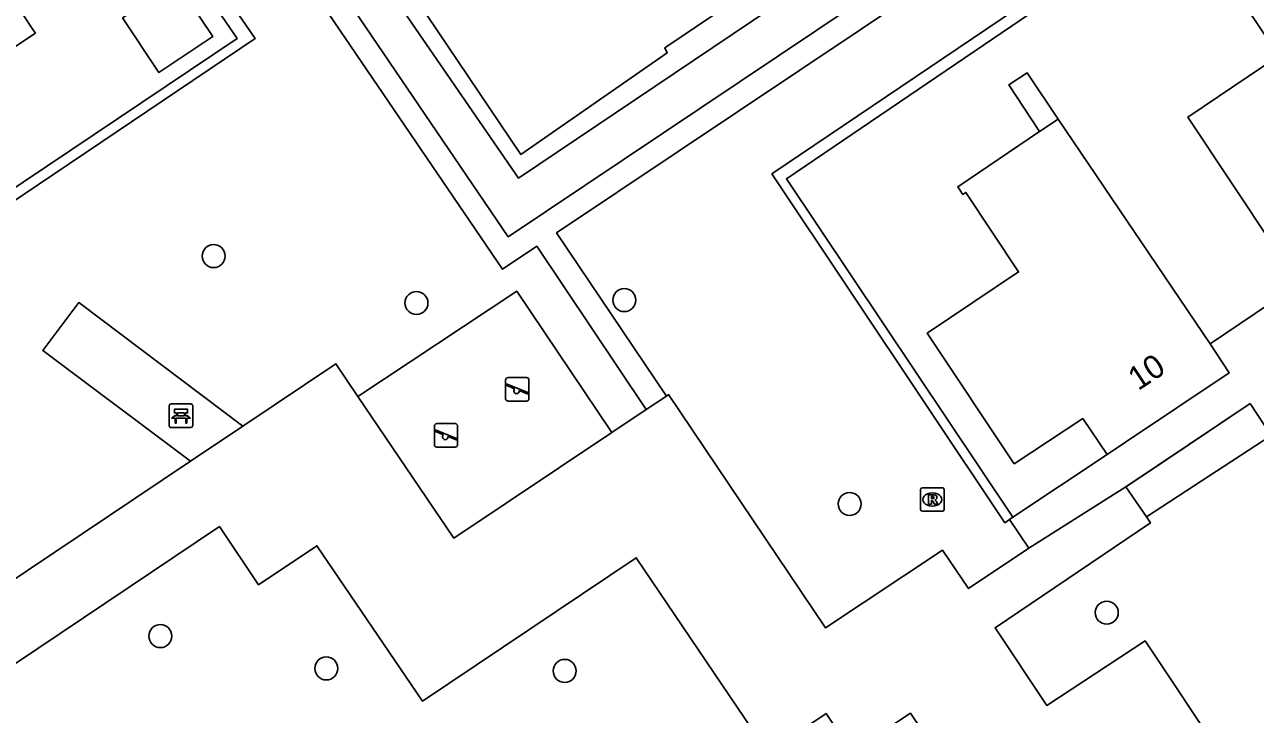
# Model space of a CAD drawing. Extents: x 158797 to 159887, y 384318 to 385255.
# Drawn here: x 158996.3 to 159048.7, y 384605 to 384634.4 of the extents above; entities that cross this region are included whole.
import ezdxf

# ---------------------------------------------------------------- set-up
doc = ezdxf.new("R2010")
doc.units = 0
for name, color, linetype in [('IMGEO_Bank', 7, 'Continuous'), ('IMGEO_Boom', 7, 'Continuous'), ('IMGEO_Groenvoorziening', 7, 'Continuous'), ('IMGEO_Haag', 7, 'Continuous'), ('IMGEO_Pand', 7, 'Continuous'), ('IMGEO_Pand_nummerreeks', 7, 'Continuous'), ('IMGEO_Rijbaan_lokaal_open', 7, 'Continuous'), ('IMGEO_Rioolput', 7, 'Continuous'), ('IMGEO_Speelvoorziening', 7, 'Continuous'), ('IMGEO_Voetpad_gesloten', 7, 'Continuous'), ('IMGEO_Voetpad_halfverhard', 7, 'Continuous'), ('IMGEO_Voetpad_open', 7, 'Continuous')]:
    doc.layers.add(name, color=color, linetype=linetype)

msp = doc.modelspace()

# ---------------------------------------------------------------- linework, layer by layer
at = {"layer": 'IMGEO_Bank'}
for p, q in [((159002.463, 384617.317), (159002.463, 384618.158)), ((159002.463, 384618.158), (159002.463, 384617.317)), ((159002.538, 384618.242), (159003.379, 384618.242)), ((159003.379, 384618.242), (159002.538, 384618.242)), ((159003.463, 384618.167), (159003.463, 384617.326)), ((159003.463, 384617.326), (159003.463, 384618.167)), ((159003.16, 384617.64), (159002.767, 384617.64)), ((159002.772, 384617.748), (159002.772, 384617.854)), ((159002.816, 384617.854), (159002.816, 384617.748)), ((159003.104, 384617.86), (159002.822, 384617.86)), ((159002.822, 384617.742), (159003.104, 384617.742)), ((159003.11, 384617.748), (159003.11, 384617.854)), ((159003.154, 384617.854), (159003.154, 384617.748)), ((159003.388, 384617.242), (159002.547, 384617.242)), ((159002.547, 384617.242), (159003.388, 384617.242))]:
    msp.add_line(p, q, dxfattribs=at)
for points in [[(159002.766, 384617.86), (159002.68, 384617.86), (159002.68, 384618.021), (159003.243, 384618.021), (159003.243, 384617.86), (159003.16, 384617.86)], [(159002.71, 384617.64), (159002.568, 384617.64), (159002.68, 384617.742), (159002.766, 384617.742)], [(159002.76, 384617.633), (159002.76, 384617.426), (159002.717, 384617.426), (159002.717, 384617.633)], [(159003.16, 384617.742), (159003.243, 384617.742), (159003.355, 384617.64), (159003.216, 384617.64)], [(159003.21, 384617.633), (159003.21, 384617.426), (159003.166, 384617.426), (159003.166, 384617.633)]]:
    msp.add_lwpolyline(points, dxfattribs=at)
for centre, radius, start, end in [((159002.541, 384618.164), 0.0779, 92.4484, 184.2845), ((159002.541, 384618.164), 0.0779, 92.4484, 184.2845), ((159003.385, 384618.164), 0.0779, 2.4484, 94.2845), ((159003.385, 384618.164), 0.0779, 2.4484, 94.2845), ((159002.71, 384617.633), 0.00671, 2.8957, 87.1043), ((159002.767, 384617.633), 0.00671, 92.8957, 177.1043), ((159002.765, 384617.853), 0.00671, 2.8957, 87.1043), ((159002.765, 384617.749), 0.00671, 272.8957, 357.1043), ((159002.822, 384617.853), 0.00671, 92.8957, 177.1043), ((159002.822, 384617.749), 0.00671, 182.8957, 267.1043), ((159003.104, 384617.853), 0.00671, 2.8957, 87.1043), ((159003.104, 384617.749), 0.00671, 272.8957, 357.1043), ((159003.161, 384617.853), 0.00671, 92.8957, 177.1043), ((159003.161, 384617.749), 0.00671, 182.8957, 267.1043), ((159003.159, 384617.633), 0.00671, 2.8957, 87.1043), ((159003.216, 384617.633), 0.00671, 92.8957, 177.1043), ((159002.541, 384617.32), 0.0779, 182.4484, 274.2845), ((159002.541, 384617.32), 0.0779, 182.4484, 274.2845), ((159003.385, 384617.32), 0.0779, 272.4484, 4.2845), ((159003.385, 384617.32), 0.0779, 272.4484, 4.2845)]:
    msp.add_arc(centre, radius, start, end, dxfattribs=at)
at = {"layer": 'IMGEO_Boom'}
for centre in [(159004.352, 384624.537), (159012.985, 384622.542), (159021.831, 384622.663), (159031.422, 384613.987), (159042.368, 384609.361), (159002.086, 384608.362), (159009.147, 384606.985), (159019.295, 384606.88)]:
    msp.add_circle(centre, 0.489, dxfattribs=at)
at = {"layer": 'IMGEO_Groenvoorziening'}
msp.add_lwpolyline([(159010.495, 384618.567), (159017.257, 384623.039), (159021.302, 384617.031)], dxfattribs=at)
at = {"layer": 'IMGEO_Haag'}
for points in [[(158982.198, 384627.503), (158986.877, 384630.783), (158991.18, 384624.297), (159005.347, 384633.805), (158997.226, 384645.658), (158986.56, 384661.35), (158977.807, 384655.577), (158970.042, 384650.292), (158941.462, 384692.581), (158927.478, 384683.208), (158931.293, 384677.308), (158928.892, 384675.59), (158929.234, 384675.051), (158928.67, 384674.688)], [(158982.566, 384626.956), (158986.69, 384629.795), (158990.973, 384623.592), (159006.114, 384633.802), (158986.551, 384662.087), (158978.394, 384656.739)], [(159074.64, 384658.987), (159074.434, 384659.327), (159072.046, 384657.677), (159028.116, 384628.032), (159038.03, 384613.181), (159038.222, 384613.33)], [(159038.372, 384613.43), (159028.729, 384627.821), (159074.64, 384658.987)], [(159000.221, 384652.861), (159003.802, 384647.511), (159004.201, 384646.941), (159017.33, 384627.856), (159035.525, 384640.095)], [(159031.062, 384645.764), (159034.39, 384640.711), (159023.558, 384633.403), (159023.653, 384633.188), (159017.434, 384628.858), (159004.937, 384647.41), (159004.913, 384647.446), (159005.369, 384647.758)], [(159048.477, 384618.263), (159044.057, 384615.293), (159043.177, 384614.715)], [(159049.365, 384616.904), (159044.054, 384613.436)]]:
    msp.add_lwpolyline(points, dxfattribs=at)
at = {"layer": 'IMGEO_Pand'}
for points in [[(158991.703, 384642.063), (158994.839, 384644.19), (158998.241, 384639.175), (158995.841, 384637.547), (158997.222, 384635.511), (158996.22, 384634.844), (158996.69, 384634.138), (158996.762, 384634.03), (158993.28, 384631.711), (158993.235, 384631.778), (158992.738, 384632.525), (158988.616, 384629.78), (158986.429, 384633.035), (158983.044, 384630.761), (158980.677, 384634.281)], [(159050.433, 384638.855), (159047.117, 384636.683), (159047.338, 384636.359), (159047.443, 384636.432), (159049.695, 384633.062), (159045.826, 384630.454), (159049.515, 384624.898), (159052.429, 384626.817), (159053.468, 384625.292)], [(159000.476, 384634.674), (159002.023, 384632.35), (159004.317, 384633.878), (159002.77, 384636.201), (159000.476, 384634.674)], [(159040.305, 384630.369), (159038.975, 384632.341), (159038.199, 384631.831), (159039.511, 384629.835)], [(159040.305, 384630.369), (159039.511, 384629.835)], [(159046.764, 384620.801), (159040.305, 384630.369)], [(159039.511, 384629.835), (159036.024, 384627.492), (159036.244, 384627.165), (159036.366, 384627.247), (159038.618, 384623.867), (159034.718, 384621.253), (159038.429, 384615.697), (159041.343, 384617.618), (159042.391, 384616.096)], [(159042.391, 384616.096), (159043.171, 384616.618), (159047.583, 384619.57), (159046.764, 384620.801)]]:
    msp.add_lwpolyline(points, dxfattribs=at)
at = {"layer": 'IMGEO_Rijbaan_lokaal_open'}
for points in [[(159046.764, 384620.801), (159050.601, 384623.386), (159053.468, 384625.292)], [(159048.477, 384618.263), (159043.177, 384614.715)], [(159049.365, 384616.904), (159048.477, 384618.263)], [(159038.372, 384613.43), (159042.391, 384616.096)], [(159043.177, 384614.715), (159039.049, 384612.101)], [(159038.222, 384613.33), (159038.372, 384613.43)], [(159039.049, 384612.101), (159038.222, 384613.33)]]:
    msp.add_lwpolyline(points, dxfattribs=at)
at = {"layer": 'IMGEO_Rioolput'}
for p, q in [((159034.443, 384613.753), (159034.443, 384614.605)), ((159034.518, 384614.679), (159035.37, 384614.679)), ((159034.931, 384614.459), (159034.956, 384614.459)), ((159035.444, 384614.605), (159035.444, 384613.753)), ((159034.954, 384613.899), (159034.929, 384613.899)), ((159035.37, 384613.679), (159034.518, 384613.679))]:
    msp.add_line(p, q, dxfattribs=at)
for points in [[(159034.443, 384613.753), (159034.443, 384614.605)], [(159034.518, 384614.679), (159035.37, 384614.679)], [(159035.032, 384614.377), (159034.78, 384614.379), (159034.78, 384613.979)], [(159034.958, 384614.298), (159034.904, 384614.298), (159034.904, 384614.217)], [(159035.444, 384614.605), (159035.444, 384613.753)], [(159034.78, 384613.979), (159034.904, 384613.979), (159034.904, 384614.141), (159034.915, 384614.141)], [(159034.904, 384614.217), (159034.956, 384614.217)], [(159034.962, 384614.112), (159035.033, 384613.979), (159035.173, 384613.979), (159035.108, 384614.105)], [(159035.37, 384613.679), (159034.518, 384613.679)]]:
    msp.add_lwpolyline(points, dxfattribs=at)
for centre, radius, start, end in [((159034.52, 384614.603), 0.0765, 91.552, 178.448), ((159034.52, 384614.603), 0.0765, 91.552, 178.448), ((159034.964, 384614.202), 0.0964, 77.0061, 93.1865), ((159034.978, 384614.259), 0.0378, 276.6634, 79.6772), ((159035.031, 384614.267), 0.109, 350.3612, 89.416), ((159035.368, 384614.603), 0.0765, 1.552, 88.448), ((159035.368, 384614.603), 0.0765, 1.552, 88.448), ((159034.52, 384613.755), 0.0765, 181.552, 268.448), ((159034.52, 384613.755), 0.0765, 181.552, 268.448), ((159034.914, 384614.088), 0.0533, 26.0293, 88.6989), ((159034.94, 384614.406), 0.19, 274.7715, 282.9687), ((159035.029, 384614.267), 0.112, 277.5842, 350.9817), ((159035.013, 384614.052), 0.108, 29.5134, 73.7905), ((159035.368, 384613.755), 0.0765, 271.552, 358.448), ((159035.368, 384613.755), 0.0765, 271.552, 358.448)]:
    msp.add_arc(centre, radius, start, end, dxfattribs=at)
for centre, major_axis, ratio, start_param, end_param in [((159034.93, 384614.179), (-0.387, 0.002), 0.722429, 4.712389, 7.853982), ((159034.955, 384614.179), (-0.39, 0.002), 0.717154, 1.570796, 4.712389)]:
    msp.add_ellipse(centre, major_axis=major_axis, ratio=ratio, start_param=start_param, end_param=end_param, dxfattribs=at)
at = {"layer": 'IMGEO_Speelvoorziening'}
for p, q in [((159016.782, 384618.464), (159016.782, 384619.264)), ((159016.782, 384619.264), (159016.782, 384618.464)), ((159017.165, 384618.892), (159016.826, 384619.029)), ((159016.851, 384619.089), (159017.727, 384618.736)), ((159016.882, 384619.364), (159017.672, 384619.364)), ((159017.672, 384619.364), (159016.882, 384619.364)), ((159017.772, 384619.264), (159017.772, 384618.464)), ((159017.772, 384618.464), (159017.772, 384619.264)), ((159017.703, 384618.676), (159017.363, 384618.813)), ((159017.672, 384618.364), (159016.882, 384618.364)), ((159016.882, 384618.364), (159017.672, 384618.364)), ((159013.748, 384616.505), (159013.748, 384617.305)), ((159013.748, 384617.305), (159013.748, 384616.505)), ((159014.131, 384616.933), (159013.792, 384617.07)), ((159013.817, 384617.13), (159014.693, 384616.777)), ((159013.848, 384617.405), (159014.638, 384617.405)), ((159014.638, 384617.405), (159013.848, 384617.405)), ((159014.738, 384617.305), (159014.738, 384616.505)), ((159014.738, 384616.505), (159014.738, 384617.305)), ((159014.638, 384616.405), (159013.848, 384616.405)), ((159013.848, 384616.405), (159014.638, 384616.405)), ((159014.669, 384616.717), (159014.329, 384616.854))]:
    msp.add_line(p, q, dxfattribs=at)
for centre, radius, start, end in [((159016.882, 384619.264), 0.1, 90, 180), ((159016.882, 384619.264), 0.1, 90, 180), ((159016.839, 384619.059), 0.0327, 68.078, 248.078), ((159017.672, 384619.264), 0.1, 0, 90), ((159017.672, 384619.264), 0.1, 360, 90), ((159016.882, 384618.464), 0.1, 180, 270), ((159016.882, 384618.464), 0.1, 180, 270), ((159017.244, 384618.802), 0.12, 130.9928, 5.1632), ((159017.672, 384618.464), 0.1, 270, 0), ((159017.672, 384618.464), 0.1, 270, 0), ((159017.715, 384618.706), 0.0327, 248.078, 68.078), ((159013.848, 384617.305), 0.1, 90, 180), ((159013.848, 384617.305), 0.1, 90, 180), ((159013.805, 384617.1), 0.0327, 68.078, 248.078), ((159014.21, 384616.843), 0.12, 130.9928, 5.1632), ((159014.638, 384617.305), 0.1, 0, 90), ((159014.638, 384617.305), 0.1, 360, 90), ((159013.848, 384616.505), 0.1, 180, 270), ((159013.848, 384616.505), 0.1, 180, 270), ((159014.638, 384616.505), 0.1, 270, 0), ((159014.638, 384616.505), 0.1, 270, 0), ((159014.681, 384616.747), 0.0327, 248.078, 68.078)]:
    msp.add_arc(centre, radius, start, end, dxfattribs=at)
at = {"layer": 'IMGEO_Voetpad_gesloten'}
for points in [[(159005.601, 384617.303), (159009.56, 384619.952), (159010.495, 384618.567)], [(159021.302, 384617.031), (159014.572, 384612.532), (159010.495, 384618.567)], [(159023.621, 384618.581), (159022.769, 384618.011)], [(159039.049, 384612.101), (159036.485, 384610.388), (159035.375, 384612.023), (159030.401, 384608.711), (159023.711, 384618.641), (159023.621, 384618.581)], [(159021.302, 384617.031), (159022.769, 384618.011)], [(159003.36, 384615.803), (159005.601, 384617.303)], [(158987.724, 384616.518), (158992.964, 384608.847), (159003.36, 384615.803)], [(159043.177, 384614.715), (159044.054, 384613.436)], [(159044.054, 384613.436), (159044.228, 384613.182), (159037.615, 384608.714), (159039.816, 384605.41), (159044.001, 384608.156), (159047.314, 384603.188), (159051.455, 384605.973), (159052.578, 384604.324), (159053.4, 384604.861), (159054.5, 384603.213), (159056.994, 384604.867), (159058.651, 384602.367), (159059.496, 384602.965), (159067.874, 384590.535), (159069.539, 384591.642), (159072.876, 384586.683), (159076.198, 384588.909), (159080.104, 384583.132), (159083.425, 384585.352), (159084.526, 384583.696), (159093.592, 384589.775)], [(158982.865, 384586.399), (158981.067, 384585.23), (158976.14, 384592.72), (158981.937, 384596.604), (158981.382, 384597.442), (159004.598, 384613.022), (159006.263, 384610.544), (159008.75, 384612.205), (159013.241, 384605.599), (159022.342, 384611.7), (159027.935, 384603.411), (159030.42, 384605.073), (159031.514, 384603.428), (159034.009, 384605.081), (159037.342, 384600.126), (159040.686, 384602.342), (159043.434, 384598.175), (159032.33, 384590.682)]]:
    msp.add_lwpolyline(points, dxfattribs=at)
at = {"layer": 'IMGEO_Voetpad_halfverhard'}
for points in [[(159022.769, 384618.011), (159018.104, 384624.955), (159016.647, 384623.978), (158996.328, 384653.852), (158998.801, 384655.513)], [(159035.72, 384639.814), (159036.593, 384638.568), (159016.892, 384625.363), (159002.463, 384646.613), (158998.856, 384651.925), (159000.221, 384652.861)], [(159023.621, 384618.581), (159018.951, 384625.522), (159039.659, 384639.394), (159038.17, 384641.536)]]:
    msp.add_lwpolyline(points, dxfattribs=at)
at = {"layer": 'IMGEO_Voetpad_open'}
msp.add_lwpolyline([(159005.601, 384617.303), (158998.618, 384622.561), (158997.078, 384620.521), (159003.36, 384615.803)], dxfattribs=at)

# ---------------------------------------------------------------- texts
at = {"layer": 'IMGEO_Pand_nummerreeks'}
msp.add_text('10', height=1, rotation=33.5868, dxfattribs=at).set_placement((159043.707, 384618.785))

doc.saveas('drawing.dxf')
